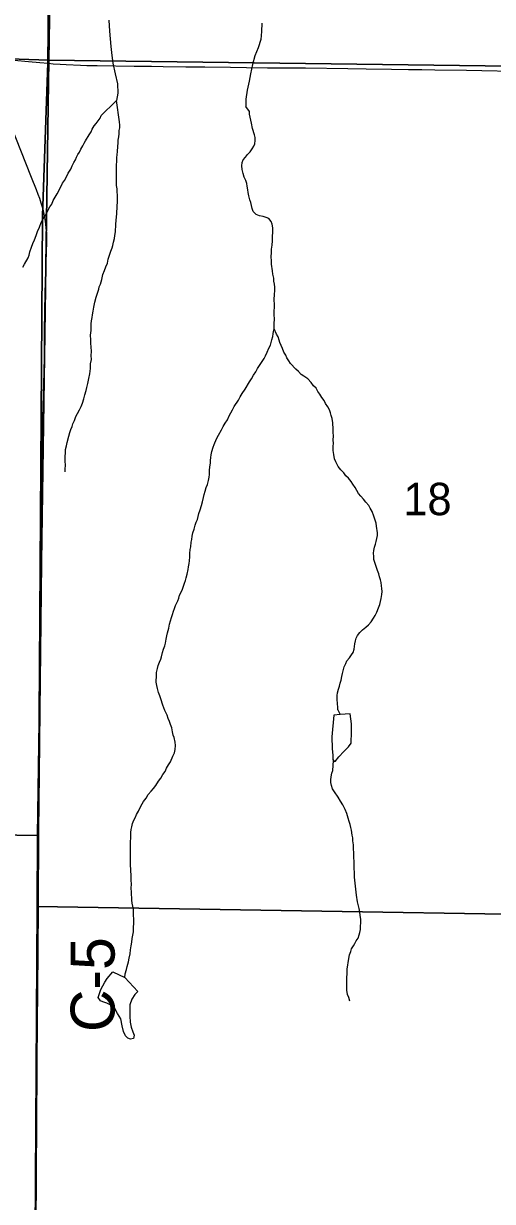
# Model space of a CAD drawing. Extents: x -8.8 to 41.4, y 0 to 34.6.
# Drawn here: x -5.453 to -4.847, y 15.077 to 16.599 of the extents above; entities that cross this region are included whole.
import ezdxf

# ---------------------------------------------------------------- set-up
doc = ezdxf.new("R2010")
doc.units = 0
for name, color, linetype in [('GM_X_Corporation', 7, 'Continuous'), ('GM_X_County_Road', 7, 'Continuous'), ('GM_X_Minor_River', 7, 'Continuous'), ('GM_X_Township_Road_Text', 7, 'Continuous'), ('GM_X_Township_Text', 7, 'Continuous')]:
    doc.layers.add(name, color=color, linetype=linetype)

msp = doc.modelspace()

# ---------------------------------------------------------------- linework, layer by layer
at = {"layer": 'GM_X_Corporation'}
for points in [[(-8.6743, 18.6925), (-8.6743, 14.1), (-5.4442, 14.1), (-5.4432, 14.2265), (-5.4429, 14.2618), (-5.4404, 14.5882), (-5.4368, 15.0446), (-5.435, 15.3164), (-5.4282, 16.3507), (-5.4212, 16.5483), (-5.4129, 17.3836), (-5.4008, 18.6369)], [(-5.4008, 18.6369), (-5.4129, 17.3836), (-5.4212, 16.5483), (-5.4282, 16.3507), (-5.435, 15.3164), (-5.4368, 15.0446), (-5.4404, 14.5882), (-5.4429, 14.2618), (-5.4432, 14.2265), (-5.4442, 14.1), (-1.8743, 14.1), (-1.8743, 18.5906)]]:
    msp.add_lwpolyline(points, dxfattribs=at)
for points in [[(-5.4036, 17.5614), (-5.4203, 16.5519), (-6.4339, 16.586), (-6.4092, 17.5696)], [(-4.4134, 17.5464), (-4.4254, 16.539), (-5.4203, 16.5519), (-5.4036, 17.5614)], [(-6.4339, 16.586), (-5.4203, 16.5519), (-5.4349, 15.5503), (-6.4479, 15.5667)], [(-5.4203, 16.5519), (-4.4254, 16.539), (-4.4369, 15.4422), (-5.4351, 15.4586), (-5.4349, 15.5503)], [(-6.4479, 15.5667), (-5.4349, 15.5503), (-5.4351, 15.4586), (-5.4406, 14.5401), (-6.4506, 14.5538)], [(-5.4351, 15.4586), (-4.4369, 15.4422), (-4.4383, 14.4395), (-5.4401, 14.4488), (-5.4406, 14.5401)]]:
    msp.add_lwpolyline(points, close=True, dxfattribs=at)
at = {"layer": 'GM_X_County_Road'}
for points in [[(-5.4647, 16.5517), (-5.4463, 16.55), (-5.4319, 16.5488), (-5.421, 16.5478)], [(-5.421, 16.5478), (-5.4146, 16.5472), (-5.4053, 16.5466), (-5.3979, 16.5462), (-5.3793, 16.5453), (-5.3712, 16.5451), (-5.3575, 16.5448), (-5.3097, 16.5441), (-5.2873, 16.5439), (-5.2724, 16.5437), (-5.2433, 16.5434), (-5.2184, 16.5431), (-5.1855, 16.5427), (-5.165, 16.5424), (-5.1376, 16.5421), (-5.1134, 16.542), (-5.0886, 16.5418), (-5.0339, 16.5409), (-5.0103, 16.5406), (-4.9774, 16.54), (-4.9557, 16.5398), (-4.9383, 16.5396), (-4.9215, 16.5393), (-4.8805, 16.5388), (-4.801, 16.537)], [(-5.4271, 16.3572), (-5.4283, 16.3621), (-5.4299, 16.3672), (-5.4319, 16.3729), (-5.4337, 16.3781), (-5.4362, 16.3844), (-5.4423, 16.4001), (-5.4831, 16.5029)], [(-5.4369, 15.0557), (-5.4367, 15.0904), (-5.4357, 15.1841), (-5.4353, 15.266), (-5.4344, 15.3501), (-5.4336, 15.4565), (-5.4331, 15.5556), (-5.4321, 15.6297), (-5.4313, 15.7117), (-5.4292, 15.9025), (-5.4287, 16.0055), (-5.4283, 16.0751), (-5.4265, 16.1343), (-5.4261, 16.1486), (-5.4255, 16.1693), (-5.4255, 16.2022), (-5.4247, 16.2512), (-5.4229, 16.3173), (-5.4229, 16.3278), (-5.4236, 16.3354), (-5.4246, 16.3439), (-5.4257, 16.3507), (-5.4271, 16.3572)]]:
    msp.add_lwpolyline(points, dxfattribs=at)
at = {"layer": 'GM_X_Minor_River'}
for points in [[(-5.3425, 16.6036), (-5.3417, 16.5892), (-5.3399, 16.5695), (-5.3387, 16.5577), (-5.3374, 16.5478), (-5.3343, 16.534), (-5.3316, 16.5211), (-5.3311, 16.5093), (-5.3325, 16.4995)], [(-5.1449, 16.5996), (-5.1456, 16.589), (-5.1462, 16.5787), (-5.1499, 16.5678), (-5.154, 16.5573), (-5.1569, 16.546), (-5.1595, 16.5343), (-5.1612, 16.5245), (-5.1638, 16.5132), (-5.1656, 16.5015), (-5.1658, 16.492)], [(-5.4164, 16.3658), (-5.4143, 16.3707), (-5.4119, 16.3748), (-5.4092, 16.3792), (-5.4051, 16.3875), (-5.4023, 16.3931), (-5.3999, 16.3965), (-5.3971, 16.4013), (-5.3951, 16.4058), (-5.3919, 16.4111), (-5.3899, 16.4152), (-5.3879, 16.4197), (-5.3855, 16.423), (-5.3843, 16.4264), (-5.3827, 16.4298), (-5.3803, 16.4331), (-5.3787, 16.4369), (-5.3763, 16.441), (-5.3743, 16.4444), (-5.3727, 16.4478), (-5.3679, 16.4552), (-5.3655, 16.4593), (-5.3643, 16.4627), (-5.3615, 16.4668), (-5.3591, 16.4702), (-5.3564, 16.4735), (-5.354, 16.4769), (-5.3524, 16.4802), (-5.3489, 16.4836), (-5.345, 16.4876), (-5.3415, 16.491), (-5.3325, 16.4995)], [(-5.3992, 16.0199), (-5.3988, 16.0237), (-5.3986, 16.0282), (-5.3992, 16.0343), (-5.3991, 16.04), (-5.3985, 16.0446), (-5.3984, 16.0487), (-5.3975, 16.0537), (-5.3966, 16.0578), (-5.3941, 16.0661), (-5.3929, 16.071), (-5.3916, 16.0748), (-5.39, 16.0785), (-5.3891, 16.0819), (-5.3871, 16.0864), (-5.3851, 16.0913), (-5.3831, 16.0954), (-5.3803, 16.1003), (-5.3783, 16.1044), (-5.3766, 16.1089), (-5.3749, 16.1142), (-5.3737, 16.1195), (-5.372, 16.1251), (-5.3711, 16.1289), (-5.3698, 16.1342), (-5.3685, 16.1406), (-5.3672, 16.1467), (-5.3662, 16.1535), (-5.3661, 16.1595), (-5.3651, 16.1652), (-5.3654, 16.1702), (-5.3652, 16.1755), (-5.3654, 16.1816), (-5.3657, 16.1858), (-5.3659, 16.1907), (-5.3662, 16.1964), (-5.3656, 16.2025), (-5.3654, 16.2112), (-5.3649, 16.215), (-5.364, 16.2195), (-5.3639, 16.2229), (-5.363, 16.2275), (-5.3621, 16.2328), (-5.3608, 16.2392), (-5.3591, 16.2456), (-5.3574, 16.2509), (-5.3557, 16.2558), (-5.3549, 16.2592), (-5.3533, 16.2625), (-5.3516, 16.2686), (-5.3503, 16.275), (-5.3482, 16.2799), (-5.3466, 16.2848), (-5.3445, 16.2897), (-5.3433, 16.2946), (-5.3399, 16.3051), (-5.3383, 16.3092), (-5.3374, 16.3126), (-5.3366, 16.3168), (-5.3353, 16.3213), (-5.3348, 16.3255), (-5.3339, 16.33), (-5.3336, 16.3395), (-5.3331, 16.3452), (-5.3321, 16.3535), (-5.3318, 16.3634), (-5.3313, 16.3687), (-5.3315, 16.3733), (-5.3314, 16.3774), (-5.3317, 16.3816), (-5.3319, 16.3858), (-5.3326, 16.39), (-5.3328, 16.395), (-5.3325, 16.4067), (-5.3327, 16.412), (-5.3323, 16.4257), (-5.3318, 16.4299), (-5.3314, 16.4333), (-5.3311, 16.4409), (-5.3307, 16.4447), (-5.3305, 16.4485), (-5.3297, 16.4526), (-5.3292, 16.4568), (-5.3291, 16.461), (-5.3286, 16.4644), (-5.3285, 16.4678), (-5.3287, 16.472), (-5.3325, 16.4995)], [(-5.1361, 16.3472), (-5.1395, 16.3485), (-5.1433, 16.3497), (-5.1482, 16.3506), (-5.1523, 16.3526), (-5.156, 16.3565), (-5.1574, 16.3604), (-5.1594, 16.368), (-5.1605, 16.3715), (-5.1618, 16.3765), (-5.1625, 16.381), (-5.1631, 16.3845), (-5.1638, 16.3891), (-5.1644, 16.3925), (-5.1658, 16.3963), (-5.1676, 16.4006), (-5.169, 16.4052), (-5.1704, 16.4105), (-5.171, 16.4151), (-5.1705, 16.4196), (-5.1689, 16.423), (-5.1661, 16.4264), (-5.1634, 16.4301), (-5.1602, 16.4334), (-5.1575, 16.4371), (-5.1555, 16.4405), (-5.1542, 16.4439), (-5.1534, 16.448), (-5.1536, 16.4518), (-5.1543, 16.4553), (-5.1571, 16.4637), (-5.1584, 16.4706), (-5.1594, 16.4744), (-5.1601, 16.4782), (-5.1611, 16.4821), (-5.161, 16.4855), (-5.1658, 16.492)], [(-5.4536, 16.2844), (-5.4516, 16.2881), (-5.4468, 16.2963), (-5.4455, 16.3001), (-5.4447, 16.3043), (-5.4426, 16.3103), (-5.4406, 16.3148), (-5.4385, 16.3197), (-5.4365, 16.3253), (-5.4348, 16.3306), (-5.432, 16.3362), (-5.4299, 16.3422), (-5.4275, 16.3467), (-5.4248, 16.3508), (-5.4231, 16.3542), (-5.4187, 16.3624), (-5.4164, 16.3658)], [(-5.2521, 15.8569), (-5.2512, 15.8607), (-5.2492, 15.8644), (-5.2476, 15.8686), (-5.2447, 15.8761), (-5.2435, 15.8795), (-5.2426, 15.8832), (-5.2414, 15.8878), (-5.24, 15.8938), (-5.2396, 15.8972), (-5.2387, 15.9018), (-5.2386, 15.9052), (-5.2381, 15.9101), (-5.2379, 15.9147), (-5.2374, 15.9196), (-5.2369, 15.923), (-5.2364, 15.929), (-5.2355, 15.9328), (-5.235, 15.937), (-5.2342, 15.9411), (-5.2325, 15.946), (-5.2312, 15.9509), (-5.2296, 15.9551), (-5.2283, 15.9585), (-5.2271, 15.9622), (-5.2262, 15.966), (-5.2246, 15.9709), (-5.2229, 15.9765), (-5.2216, 15.9814), (-5.2203, 15.9867), (-5.2195, 15.9909), (-5.2182, 15.995), (-5.2169, 15.9999), (-5.2153, 16.0037), (-5.214, 16.009), (-5.2131, 16.0131), (-5.2127, 16.0165), (-5.2125, 16.0218), (-5.212, 16.0264), (-5.2115, 16.0313), (-5.2114, 16.0347), (-5.2109, 16.0385), (-5.2104, 16.0419), (-5.2095, 16.0461), (-5.2079, 16.0517), (-5.2066, 16.0551), (-5.2034, 16.0626), (-5.201, 16.0675), (-5.197, 16.0742), (-5.195, 16.0787), (-5.1922, 16.0828), (-5.1894, 16.0873), (-5.187, 16.0922), (-5.185, 16.0963), (-5.183, 16.1001), (-5.1806, 16.1042), (-5.175, 16.1124), (-5.173, 16.1169), (-5.1702, 16.121), (-5.1667, 16.1266), (-5.1611, 16.1363), (-5.1583, 16.14), (-5.1559, 16.1449), (-5.1527, 16.1494), (-5.1507, 16.1535), (-5.148, 16.1572), (-5.142, 16.1665), (-5.1404, 16.1699), (-5.138, 16.1744), (-5.1359, 16.1797), (-5.1339, 16.1838), (-5.1322, 16.1906), (-5.1306, 16.1947), (-5.1305, 16.1981), (-5.13, 16.2015), (-5.1292, 16.2049), (-5.1291, 16.2083), (-5.1289, 16.2121), (-5.1288, 16.2167), (-5.129, 16.2235), (-5.1286, 16.2368), (-5.1289, 16.2418), (-5.1286, 16.2498), (-5.1282, 16.2535), (-5.1284, 16.2585), (-5.1287, 16.2623), (-5.1293, 16.2665), (-5.1296, 16.2703), (-5.1306, 16.2753), (-5.1312, 16.2798), (-5.1325, 16.2882), (-5.1327, 16.2924), (-5.133, 16.2978), (-5.1324, 16.3034), (-5.1323, 16.3076), (-5.1318, 16.3129), (-5.1312, 16.3186), (-5.1308, 16.3353), (-5.1318, 16.3399), (-5.1328, 16.3433), (-5.1361, 16.3472)], [(-5.0185, 15.8123), (-5.015, 15.8157), (-5.0107, 15.8193), (-5.0072, 15.8223), (-5.0037, 15.8264), (-5.0009, 15.8308), (-4.9985, 15.8342), (-4.9965, 15.8387), (-4.9941, 15.8443), (-4.9928, 15.8488), (-4.9916, 15.8526), (-4.9907, 15.8564), (-4.9898, 15.8617), (-4.9897, 15.8655), (-4.9899, 15.8693), (-4.9906, 15.8727), (-4.9909, 15.8769), (-4.9919, 15.8804), (-4.9929, 15.8842), (-4.994, 15.8884), (-4.9954, 15.8926), (-4.9978, 15.8991), (-4.9992, 15.903), (-5.0003, 15.9068), (-5.0005, 15.9106), (-5.0008, 15.9148), (-5.0003, 15.9182), (-4.9994, 15.9227), (-4.9982, 15.9265), (-4.9973, 15.9299), (-4.9965, 15.9337), (-4.9956, 15.9378), (-4.9955, 15.9413), (-4.9968, 15.9497), (-4.9974, 15.9535), (-4.9984, 15.9577), (-5.0002, 15.9627), (-5.0027, 15.9688), (-5.0052, 15.9731), (-5.0066, 15.9765), (-5.0107, 15.9808), (-5.0136, 15.9847), (-5.0173, 15.9886), (-5.0202, 15.9921), (-5.0246, 15.9998), (-5.0275, 16.0041), (-5.0297, 16.0076), (-5.0329, 16.0118), (-5.0363, 16.015), (-5.0392, 16.0189), (-5.0429, 16.0228), (-5.0462, 16.027), (-5.0494, 16.0328), (-5.0512, 16.0367), (-5.0522, 16.0424), (-5.0528, 16.0477), (-5.0527, 16.0527), (-5.0525, 16.0569), (-5.0528, 16.0607), (-5.0526, 16.0664), (-5.0529, 16.0709), (-5.0528, 16.0751), (-5.0533, 16.0835), (-5.0543, 16.0888), (-5.0553, 16.0927), (-5.0564, 16.0961), (-5.0578, 16.0999), (-5.0599, 16.1038), (-5.0628, 16.1084), (-5.0646, 16.1123), (-5.0675, 16.1162), (-5.0701, 16.1204), (-5.0726, 16.1239), (-5.0748, 16.1282), (-5.0781, 16.1313), (-5.0814, 16.1356), (-5.0855, 16.1402), (-5.0907, 16.1434), (-5.094, 16.1458), (-5.0977, 16.1497), (-5.101, 16.1525), (-5.108, 16.1599), (-5.1102, 16.1634), (-5.1128, 16.1672), (-5.1142, 16.1707), (-5.1164, 16.1745), (-5.1181, 16.1795), (-5.1199, 16.1834), (-5.1217, 16.1869), (-5.1227, 16.1903), (-5.1241, 16.1942), (-5.1259, 16.198), (-5.1292, 16.2049)], [(-5.322, 15.3669), (-5.3213, 15.3713), (-5.32, 15.377), (-5.3191, 15.3812), (-5.3174, 15.3872), (-5.3165, 15.3917), (-5.3152, 15.3974), (-5.3147, 15.4023), (-5.3138, 15.4076), (-5.3129, 15.4125), (-5.3124, 15.4171), (-5.3115, 15.4216), (-5.3106, 15.4258), (-5.3102, 15.4425), (-5.3108, 15.447), (-5.3109, 15.4547), (-5.3116, 15.4588), (-5.3126, 15.4627), (-5.3129, 15.4665), (-5.3133, 15.4771), (-5.3136, 15.4821), (-5.3134, 15.4874), (-5.3137, 15.4923), (-5.3139, 15.4969), (-5.3144, 15.5068), (-5.3146, 15.5114), (-5.3145, 15.5155), (-5.3148, 15.5205), (-5.3145, 15.5311), (-5.3147, 15.5353), (-5.3142, 15.5543), (-5.3137, 15.5581), (-5.3128, 15.5615), (-5.312, 15.5656), (-5.3103, 15.5701), (-5.3083, 15.5739), (-5.3067, 15.5773), (-5.3043, 15.5818), (-5.3011, 15.5881), (-5.2979, 15.5941), (-5.2943, 15.5986), (-5.2916, 15.6031), (-5.288, 15.6075), (-5.2849, 15.6108), (-5.2817, 15.6149), (-5.2786, 15.6202), (-5.2754, 15.6243), (-5.273, 15.6288), (-5.2698, 15.6328), (-5.2682, 15.637), (-5.2654, 15.6415), (-5.263, 15.6452), (-5.2598, 15.6527), (-5.2578, 15.6572), (-5.2569, 15.6614), (-5.2564, 15.6663), (-5.257, 15.6709), (-5.2584, 15.6766), (-5.2594, 15.68), (-5.2604, 15.6843), (-5.2614, 15.6892), (-5.2628, 15.6938), (-5.2642, 15.6973), (-5.266, 15.7015), (-5.2674, 15.7057), (-5.2703, 15.7115), (-5.2717, 15.715), (-5.2727, 15.7184), (-5.2755, 15.7269), (-5.2769, 15.7307), (-5.2783, 15.7349), (-5.2797, 15.7403), (-5.2807, 15.7441), (-5.2814, 15.7483), (-5.2811, 15.7574), (-5.281, 15.7608), (-5.2797, 15.7661), (-5.2789, 15.7699), (-5.2772, 15.774), (-5.2756, 15.7778), (-5.2747, 15.7812), (-5.2731, 15.7868), (-5.2718, 15.791), (-5.2702, 15.7951), (-5.2693, 15.7985), (-5.2684, 15.8038), (-5.2675, 15.808), (-5.267, 15.8121), (-5.2653, 15.8181), (-5.2641, 15.8231), (-5.2628, 15.8276), (-5.2615, 15.8317), (-5.2603, 15.8355), (-5.259, 15.84), (-5.2578, 15.8434), (-5.2566, 15.8472), (-5.2537, 15.8535), (-5.2521, 15.8569)], [(-5.0467, 15.7126), (-5.0467, 15.7128), (-5.047, 15.7162), (-5.0473, 15.7204), (-5.0479, 15.7265), (-5.0477, 15.7311), (-5.0473, 15.7345), (-5.046, 15.7394), (-5.0447, 15.7432), (-5.0439, 15.7469), (-5.0426, 15.7507), (-5.0417, 15.7556), (-5.0409, 15.7594), (-5.0396, 15.7647), (-5.0387, 15.7681), (-5.0367, 15.7726), (-5.0351, 15.7759), (-5.0319, 15.7797), (-5.0292, 15.7834), (-5.0272, 15.7867), (-5.0259, 15.7909), (-5.025, 15.7977), (-5.0241, 15.8019), (-5.0233, 15.8052), (-5.0216, 15.8086), (-5.0185, 15.8123)], [(-5.0438, 15.7065), (-5.0518, 15.7056), (-5.0546, 15.6776), (-5.0542, 15.6628), (-5.0534, 15.6537), (-5.0532, 15.6483), (-5.0524, 15.6472), (-5.0502, 15.6456), (-5.0455, 15.6519), (-5.0392, 15.6586), (-5.0329, 15.6648), (-5.0294, 15.6693)], [(-5.0467, 15.7126), (-5.0438, 15.7065)], [(-5.0294, 15.6693), (-5.0293, 15.6841), (-5.029, 15.6943), (-5.0309, 15.7073), (-5.0438, 15.7065)], [(-5.0313, 15.3362), (-5.0326, 15.3408), (-5.0344, 15.345), (-5.035, 15.3504), (-5.0353, 15.3553), (-5.0351, 15.3614), (-5.0354, 15.3656), (-5.0348, 15.3728), (-5.0346, 15.3777), (-5.0327, 15.3913), (-5.0318, 15.3962), (-5.0302, 15.4004), (-5.029, 15.4038), (-5.0266, 15.4075), (-5.025, 15.4109), (-5.023, 15.4142), (-5.0206, 15.4176), (-5.0193, 15.4217), (-5.0185, 15.4251), (-5.0176, 15.4289), (-5.0175, 15.4327), (-5.017, 15.438), (-5.0173, 15.4418), (-5.0179, 15.4475), (-5.0185, 15.4513), (-5.0191, 15.4559), (-5.0205, 15.4609), (-5.0215, 15.4647), (-5.0228, 15.4731), (-5.0237, 15.4808), (-5.0243, 15.4887), (-5.0252, 15.4964), (-5.0254, 15.5028), (-5.0256, 15.507), (-5.0259, 15.5127), (-5.0257, 15.5169), (-5.026, 15.5215), (-5.0262, 15.5287), (-5.0265, 15.5321), (-5.0267, 15.5382), (-5.0273, 15.5435), (-5.0275, 15.5474), (-5.0282, 15.5508), (-5.0292, 15.5569), (-5.0302, 15.5607), (-5.0308, 15.5645), (-5.0323, 15.5684), (-5.0333, 15.5726), (-5.0354, 15.5787), (-5.0375, 15.5837), (-5.0404, 15.5899), (-5.0433, 15.5945), (-5.0462, 15.5996), (-5.0513, 15.6065), (-5.0538, 15.6104), (-5.0552, 15.6146), (-5.0559, 15.6185), (-5.0558, 15.6223), (-5.0553, 15.626), (-5.0544, 15.6306), (-5.0531, 15.6343), (-5.0524, 15.6472)], [(-5.34, 15.3311), (-5.3453, 15.3335), (-5.3505, 15.3352), (-5.3535, 15.3368), (-5.3564, 15.3411), (-5.3531, 15.3512), (-5.3479, 15.3609), (-5.3447, 15.3654), (-5.3376, 15.3743), (-5.322, 15.3669)], [(-5.322, 15.3669), (-5.305, 15.3486), (-5.3089, 15.3446), (-5.3129, 15.339), (-5.3154, 15.3315), (-5.3155, 15.3254), (-5.3154, 15.317), (-5.3149, 15.3091), (-5.3136, 15.3026), (-5.3115, 15.2968), (-5.3097, 15.2922), (-5.3106, 15.288), (-5.3148, 15.287), (-5.3182, 15.2883), (-5.3211, 15.2914), (-5.3236, 15.2972), (-5.3253, 15.3044), (-5.3269, 15.3132), (-5.3313, 15.3202), (-5.3349, 15.3267), (-5.34, 15.3311)]]:
    msp.add_lwpolyline(points, dxfattribs=at)

# ---------------------------------------------------------------- texts
at = {"layer": 'GM_X_Township_Road_Text'}
msp.add_text('C-5', height=0.05682, rotation=90, dxfattribs=at).set_placement((-5.3351, 15.2964))
at = {"layer": 'GM_X_Township_Text'}
msp.add_text('18', height=0.04186, rotation=0, dxfattribs=at).set_placement((-4.9622, 15.964))

doc.saveas('drawing.dxf')
